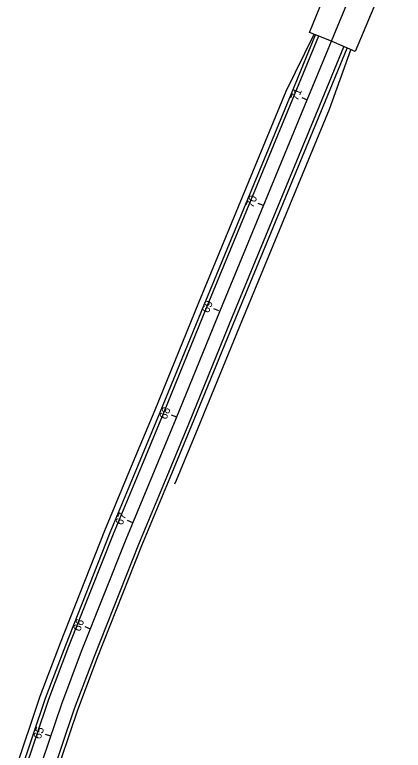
# Model space of a CAD drawing. Extents: x 2318076 to 2324211, y 613525 to 629939.
# Drawn here: x 2318678 to 2319018, y 621371 to 622014 of the extents above; entities that cross this region are included whole.
import ezdxf

# ---------------------------------------------------------------- set-up
doc = ezdxf.new("R2010")
doc.units = 0
for name, color, linetype in [('BR_X_Slab_Object', 7, 'Continuous'), ('GE_P_CL_50', 7, 'Continuous'), ('PV_P_EOP', 7, 'Continuous'), ('PV_P_Shoulder', 7, 'Continuous'), ('RD_X_GR_Lt', 7, 'Continuous'), ('RD_X_GR_Rt', 7, 'Continuous')]:
    doc.layers.add(name, color=color, linetype=linetype)

msp = doc.modelspace()

# ---------------------------------------------------------------- linework, layer by layer
at = {"layer": 'BR_X_Slab_Object'}
msp.add_lwpolyline([(2318975.86, 621982.32), (2318966.58, 621986.27), (2318955.8, 621991.11), (2318945.09, 621995.46), (2318936.06, 621999.02), (2318976.92, 622099.11), (2318986.65, 622094.78), (2318995.68, 622091.22), (2319006.8, 622086.52), (2319018.06, 622082.33), (2318975.86, 621982.32)], dxfattribs=at)
at = {"layer": 'GE_P_CL_50'}
for p, q in [((2318934.13, 621939.89), (2318929.52, 621941.82)), ((2318895.62, 621847.6), (2318891, 621849.52)), ((2318856.78, 621755.46), (2318852.18, 621757.42)), ((2318819.76, 621662.57), (2318815.11, 621664.39)), ((2318781.39, 621570.22), (2318776.78, 621572.14)), ((2318744.29, 621477.36), (2318739.64, 621479.2)), ((2318709.57, 621383.6), (2318704.84, 621385.2))]:
    msp.add_line(p, q, dxfattribs=at)
msp.add_lwpolyline([(2318697.08, 621346.57), (2318719.13, 621411.93), (2318736.61, 621457.99), (2318775.51, 621556.07), (2318800.25, 621615.57), (2318819.28, 621661.33), (2318857.56, 621755.12), (2318934.06, 621939.92), (2318972.07, 622032.4)], dxfattribs=at)
at = {"layer": 'PV_P_EOP'}
for points in [[(2318685.64, 621350.2), (2318707.83, 621415.98), (2318725.42, 621462.33), (2318764.39, 621560.59), (2318789.17, 621620.18), (2318808.18, 621665.9), (2318846.46, 621759.68), (2318922.97, 621944.49), (2318944.08, 621995.87)], [(2318708.52, 621342.94), (2318730.43, 621407.88), (2318747.8, 621453.65), (2318786.63, 621551.55), (2318811.33, 621610.96), (2318830.38, 621656.76), (2318868.66, 621750.56), (2318945.16, 621935.34), (2318966.16, 621986.46)]]:
    msp.add_lwpolyline(points, dxfattribs=at)
at = {"layer": 'PV_P_Shoulder'}
for points in [[(2318682.78, 621351.11), (2318705.01, 621416.99), (2318722.63, 621463.42), (2318761.61, 621561.71), (2318786.4, 621621.33), (2318805.41, 621667.04), (2318843.68, 621760.82), (2318920.2, 621945.64), (2318941.31, 621997.01)], [(2318711.38, 621342.03), (2318733.25, 621406.87), (2318750.59, 621452.56), (2318789.41, 621550.43), (2318814.1, 621609.81), (2318833.15, 621655.62), (2318871.43, 621749.42), (2318947.93, 621934.2), (2318968.94, 621985.32)]]:
    msp.add_lwpolyline(points, dxfattribs=at)
at = {"layer": 'RD_X_GR_Lt'}
msp.add_line((2318915.58, 621947.54), (2318940, 621997.47), dxfattribs=at)
msp.add_lwpolyline([(2318678.02, 621352.63), (2318700.3, 621418.68), (2318717.96, 621465.23), (2318756.98, 621563.6), (2318781.78, 621623.25), (2318800.79, 621668.95), (2318839.06, 621762.72), (2318915.58, 621947.54)], dxfattribs=at)
at = {"layer": 'RD_X_GR_Rt'}
msp.add_line((2318953.48, 621931.91), (2318972.19, 621983.88), dxfattribs=at)
msp.add_lwpolyline([(2318818.27, 621604.22), (2318819.64, 621607.51), (2318838.7, 621653.33), (2318876.98, 621747.14), (2318953.48, 621931.91)], dxfattribs=at)

# ---------------------------------------------------------------- texts
at = {"layer": 'GE_P_CL_50'}
for s, rotation, p in [('71', 67.23321, (2318925.5, 621938.7)), ('70', 67.45942, (2318886.48, 621845.16)), ('69', 66.84295, (2318847.63, 621753.14)), ('68', 68.6645, (2318810.73, 621660.06)), ('67', 67.42254, (2318772.19, 621567.63)), ('66', 68.36598, (2318735.19, 621474.75)), ('65', 71.35754, (2318700.63, 621380.54))]:
    msp.add_text(s, height=7, rotation=rotation, dxfattribs=at).set_placement(p)

doc.saveas('drawing.dxf')
